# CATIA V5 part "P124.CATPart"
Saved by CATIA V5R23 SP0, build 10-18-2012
Part number: P124
Definition: Matrice d'emboutissage
Bounding box of the stored display mesh (mm): x -179.995 to 179.995, y -179.978 to 179.978, z -18 to 14
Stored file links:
  C:\wamp\www\COURS\CONCEPTION GMP1\TITRE 02-SEMESTRE 2\03-TP7-PRESSE MECANIQUE\eleve\P124.CATPart
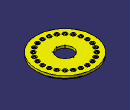
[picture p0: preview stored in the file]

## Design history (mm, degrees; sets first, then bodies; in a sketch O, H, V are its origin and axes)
Body1 (main body)
  Sketch1 on yz-plane, origin (0, 0, 0), H (0, 1, 0), V (0, 0, 1)
    line L1 (0, 0) -> (-111, 0)
    point P1 (-111, 0)
    line L2 (-111, 0) -> (-121, -18)
    point P2 (-121, -18)
    line L3 (-121, -18) -> (-161, -18)
    line L4 (-161, -18) -> (-169, 0)
    point P4 (-169, 0)
    line L5 (-169, 0) -> (-180, 0)
    line L6 (-180, 0) -> (-180, 14)
    line L7 (-180, 14) -> (0, 14)
    point P7 (0, 14)
    line L8 (0, 14) -> (0, 0)
    distance L1 L7 = 14
    distance L3 L1 = 18
    length L3 = 40
    distance P1 L8 = 111
    distance P2 L8 = 121
    length L7 = 180
    angle L5 L4 = 113.9625
    horizontal: L1 H, L3 H, L5 H, L7 H
    coincidence: P4 H, P7 V
    vertical: L6 V, L8 V
  Shaft1: profile Sketch1, axis Sketch1.V, angle 360
  Sketch2 on zx-plane, origin (0, 0, 0), H (-1, 0, 0), V (0, 0, 1)
    construction line L1 (-141, 77.6015) -> (-141, -53.8358)
    point P3 (-141, 62.3982)
    line L2 (-141, 62.3982) -> (-154, 62.3982)
    line L3 (-154, 62.3982) -> (-154, 11)
    point P5 (-154, 11)
    arc A1 centre (-141, 5) radius 9 from (-141, 14) to (-147.7082, 11) ccw
    point P6 (-141, 5)
    point P7 (-141, 14)
    point P8 (-147.7082, 11)
    reference projected line E1 (-180, 14) -> (180, 14) from edge [face of Shaft1 | face of Shaft1]
    line L4 (-154, 11) -> (-147.7082, 11)
    point P9 (-147.7082, 11)
    reference projected line E2 (-180, 14) -> (180, 14) from edge [face of Shaft1 | face of Shaft1]
    line L5 (-141, 62.3982) -> (-141, 14)
    distance L1 V = 141
    radius A1 = 9
    distance P5 E1 = 3
    distance L3 L1 = 13
    vertical: L1 V, L3 V, L5 V
    coincidence: P3 L1, P6 L1, P7 L1, P8 L4, P8 P9
    horizontal: L2 H, L4 H
    tangency: A1 E2
  Groove1: profile Sketch2, axis edge of Sketch2, angle 360
  Fillet1: radius 3, on face of Groove1
  CircPattern1: of Groove1, Sketch2, Fillet1, instances 25, angular step 15, axis from face of Shaft1
  Sketch3 on face of Shaft1, origin (0, 0, 14), H (1, 0, 0), V (0, 1, 0)
    point P1 (0, 0)
  Hole1: placed by Sketch3, at (0, 0, 14) direction (0, 0, -1), diameter 100, through (limit type 3)
  Sketch4 on face of Shaft1, origin (0, 0, 0), H (1, 0, 0), V (0, -1, 0)
    point P1 (0, 54)
    distance O P1 = 54
    coincidence: P1 V
  Hole2: placed by Sketch4, at (0, -54, 0) direction (0, 0, 1), diameter 6, through (limit type 3)
  Sketch5 on face of Shaft1, origin (0, 0, 0), H (1, 0, 0), V (0, -1, 0)
    point P1 (0, -54)
    point P2 (38.1838, 38.1838)
    construction line L1 (0, 0) -> (59.2116, 59.2116)
    point P4 (-38.1838, 38.1838)
    construction line L2 (0, 0) -> (-58.3125, 58.3125)
    distance P1 O = 54
    distance P2 O = 54
    angle L1 V = 45
    distance P4 O = 54
    angle L2 V = 45
    coincidence: P1 V, L1 P2, L2 P4
  UserPattern1: of Hole2, copies 4, at the points of Sketch5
